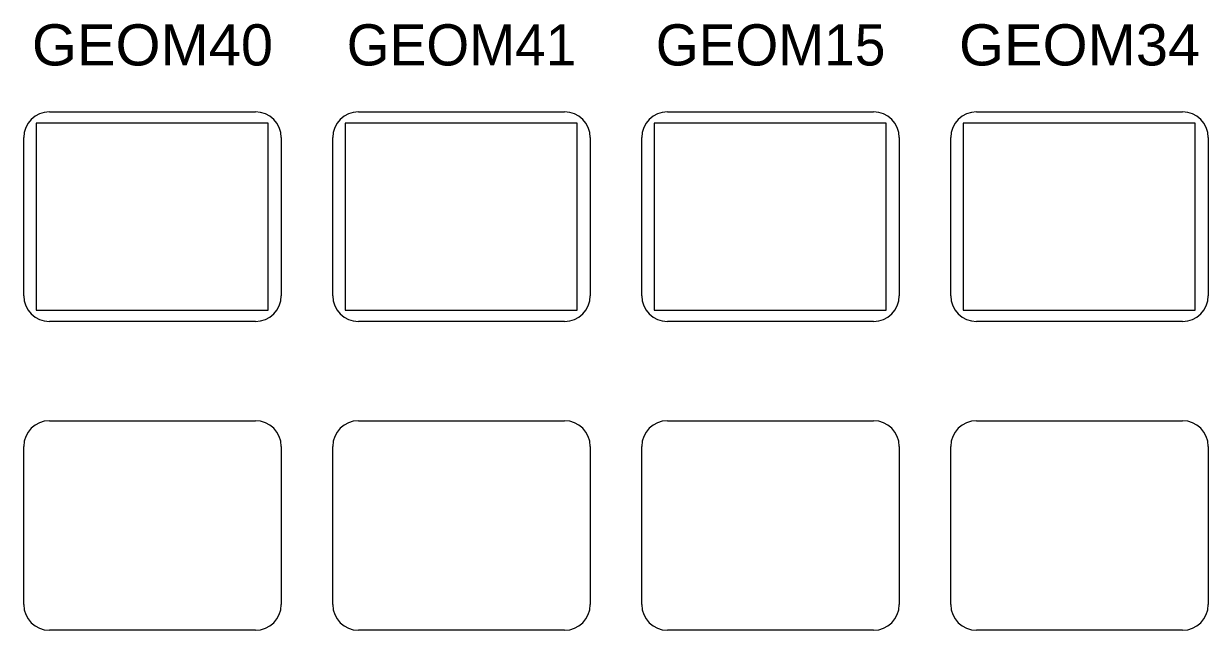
# Model space of a CAD drawing. Extents: x 95935 to 95946.4, y 95971.2 to 95974.7.
# Drawn here: x 95938.686 to 95940.986, y 95971.925 to 95973.103 of the extents above; entities that cross this region are included whole.
import ezdxf
from ezdxf.enums import TextEntityAlignment as Align

# ---------------------------------------------------------------- set-up
doc = ezdxf.new("R2010")
doc.units = 0
doc.header["$LTSCALE"] = 0.032
doc.layers.add('1', color=7, linetype='Continuous', lineweight=13)
doc.layers.add('2', color=7, linetype='Continuous', lineweight=13)
doc.layers.add('20', color=7, linetype='Continuous')

msp = doc.modelspace()

# ---------------------------------------------------------------- linework, layer by layer
at = {"layer": '1'}
for p, q in [((95938.7357, 95972.9318), (95939.1357, 95972.9318)), ((95939.3357, 95972.9318), (95939.7357, 95972.9318)), ((95939.9357, 95972.9318), (95940.3357, 95972.9318)), ((95940.5357, 95972.9318), (95940.9357, 95972.9318)), ((95938.6857, 95972.5747), (95938.6857, 95972.8818)), ((95939.1857, 95972.8818), (95939.1857, 95972.5747)), ((95939.2857, 95972.5747), (95939.2857, 95972.8818)), ((95939.7857, 95972.8818), (95939.7857, 95972.5747)), ((95939.8857, 95972.5747), (95939.8857, 95972.8818)), ((95940.3857, 95972.8818), (95940.3857, 95972.5747)), ((95940.4857, 95972.5747), (95940.4857, 95972.8818)), ((95940.9857, 95972.8818), (95940.9857, 95972.5747)), ((95939.1357, 95972.5247), (95938.7357, 95972.5247)), ((95939.7357, 95972.5247), (95939.3357, 95972.5247)), ((95940.3357, 95972.5247), (95939.9357, 95972.5247)), ((95940.9357, 95972.5247), (95940.5357, 95972.5247)), ((95938.7357, 95972.3318), (95939.1357, 95972.3318)), ((95939.3357, 95972.3318), (95939.7357, 95972.3318)), ((95939.9357, 95972.3318), (95940.3357, 95972.3318)), ((95940.5357, 95972.3318), (95940.9357, 95972.3318)), ((95938.6857, 95971.9747), (95938.6857, 95972.2818)), ((95939.1857, 95972.2818), (95939.1857, 95971.9747)), ((95939.2857, 95971.9747), (95939.2857, 95972.2818)), ((95939.7857, 95972.2818), (95939.7857, 95971.9747)), ((95939.8857, 95971.9747), (95939.8857, 95972.2818)), ((95940.3857, 95972.2818), (95940.3857, 95971.9747)), ((95940.4857, 95971.9747), (95940.4857, 95972.2818)), ((95940.9857, 95972.2818), (95940.9857, 95971.9747)), ((95939.1357, 95971.9247), (95938.7357, 95971.9247)), ((95939.7357, 95971.9247), (95939.3357, 95971.9247)), ((95940.3357, 95971.9247), (95939.9357, 95971.9247)), ((95940.9357, 95971.9247), (95940.5357, 95971.9247))]:
    msp.add_line(p, q, dxfattribs=at)
for centre, start, end in [((95938.7357, 95972.8818), 90, 180), ((95939.1357, 95972.8818), 0, 90), ((95939.3357, 95972.8818), 90, 180), ((95939.7357, 95972.8818), 0, 90), ((95939.9357, 95972.8818), 90, 180), ((95940.3357, 95972.8818), 0, 90), ((95940.5357, 95972.8818), 90, 180), ((95940.9357, 95972.8818), 0, 90), ((95938.7357, 95972.5747), 180, 270), ((95939.1357, 95972.5747), 270, 0), ((95939.3357, 95972.5747), 180, 270), ((95939.7357, 95972.5747), 270, 0), ((95939.9357, 95972.5747), 180, 270), ((95940.3357, 95972.5747), 270, 0), ((95940.5357, 95972.5747), 180, 270), ((95940.9357, 95972.5747), 270, 0), ((95938.7357, 95972.2818), 90, 180), ((95939.1357, 95972.2818), 0, 90), ((95939.3357, 95972.2818), 90, 180), ((95939.7357, 95972.2818), 0, 90), ((95939.9357, 95972.2818), 90, 180), ((95940.3357, 95972.2818), 0, 90), ((95940.5357, 95972.2818), 90, 180), ((95940.9357, 95972.2818), 0, 90), ((95938.7357, 95971.9747), 180, 270), ((95939.1357, 95971.9747), 270, 0), ((95939.3357, 95971.9747), 180, 270), ((95939.7357, 95971.9747), 270, 0), ((95939.9357, 95971.9747), 180, 270), ((95940.3357, 95971.9747), 270, 0), ((95940.5357, 95971.9747), 180, 270), ((95940.9357, 95971.9747), 270, 0)]:
    msp.add_arc(centre, 0.05, start, end, dxfattribs=at)
at = {"layer": '2'}
for points in [[(95939.1601, 95972.9099), (95938.7097, 95972.9099), (95938.7097, 95972.5468), (95939.1601, 95972.5468)], [(95939.7601, 95972.9099), (95939.3097, 95972.9099), (95939.3097, 95972.5468), (95939.7601, 95972.5468)], [(95940.3601, 95972.9099), (95939.9097, 95972.9099), (95939.9097, 95972.5468), (95940.3601, 95972.5468)], [(95940.9601, 95972.9099), (95940.5097, 95972.9099), (95940.5097, 95972.5468), (95940.9601, 95972.5468)]]:
    msp.add_lwpolyline(points, close=True, dxfattribs=at)

# ---------------------------------------------------------------- texts
at = {"layer": '20', "width": 1.05}
for s, p in [('GEOM40', (95938.9358, 95973.022)), ('GEOM34', (95940.7358, 95973.022))]:
    msp.add_text(s, height=0.08, dxfattribs=at).set_placement(p, align=Align.CENTER)
at = {"layer": '20'}
for s, p in [('GEOM41', (95939.5358, 95973.022)), ('GEOM15', (95940.1359, 95973.022))]:
    msp.add_text(s, height=0.08, dxfattribs=at).set_placement(p, align=Align.CENTER)

doc.saveas('drawing.dxf')
